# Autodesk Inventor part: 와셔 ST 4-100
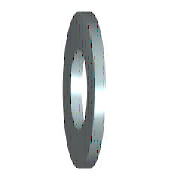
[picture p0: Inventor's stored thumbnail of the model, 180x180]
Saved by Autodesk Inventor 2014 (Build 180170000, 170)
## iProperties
IsCustomPart: 0
Created: 2012-02
Part Number: 와셔 ST 4-100
Material: 일반
Description: 평면 와셔 - 일반 시리즈 - 제품 등급 C
Document SubType Name: Modeling
Standard: ISO 7091
Designer: mduedu
Standard Revision: Second edition 2000-06-01
Standards Organization: ISO
Language: ko-KR
Size Designation: ST 4 - 100 HV
Categories: <MemberInstance><Categories><Category DisplayName="조임쇠" InternalName="e4da775c-781d-43d5-af7c-5136215cf5a6" Mnemonic="FSTN"><Category DisplayName="와셔" InternalN
Density: 1 g/cm^3
Mass: 0.0626355 g
Surface Area: 1.70824 cm^2
Volume: 0.0626355 cm^3
Appearance: 파란색 - 벽 페인트 - 광택
Author: mduedu
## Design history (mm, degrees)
sketch "스케치"
  geometry: C1 r 5 at (0, 0); C2 r 2.25 at (0, 0); 1 further point
  constraints: 2 centre point, 2 coincident
  dimensions: "d0" = 4.5 diameter of C2 (= SD1); "d1" = 10 diameter of C1 (= SD2)
extrude "본체" new body sketch "스케치" distance "d2" = 1 (= SD); taper "d3" = 0 deg
workaxis "Work Axis1"
workplane "Work Plane1"
body "Solid1"
other parameters: "SD1" = 4.5 [user parameter; used in 1 equation term], "SD2" = 10 [user parameter; used in 1 equation term], "SD" = 1 [user parameter; used in 1 equation term], "d4" = 0, "d5" = 0, "d6" = 0, "d7" = 0, "NND" = 4 [user parameter]
